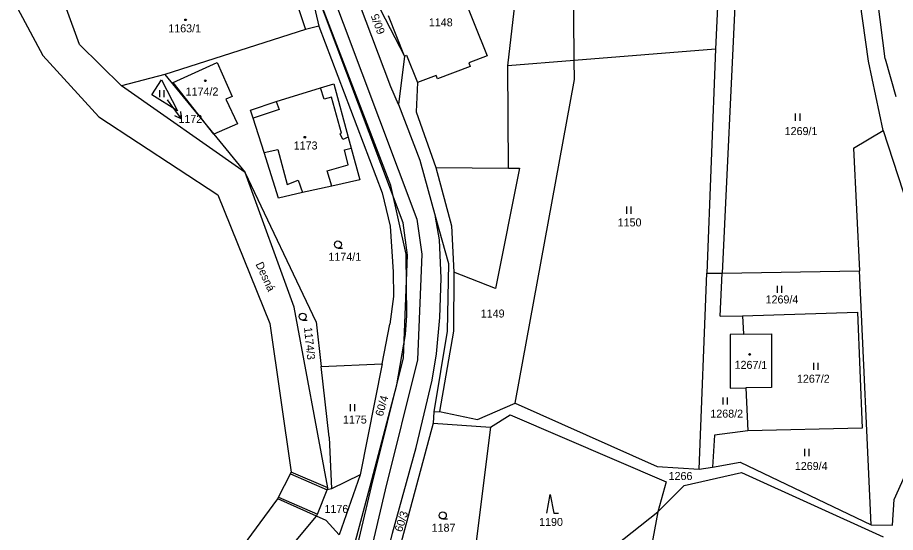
# Model space of a CAD drawing. Extents: x -670359 to -668019, y -978807 to -976674.
# Drawn here: x -670237.2 to -670050.9, y -978052.1 to -977942.9 of the extents above; entities that cross this region are included whole.
import ezdxf

# ---------------------------------------------------------------- set-up
doc = ezdxf.new("R2010")
doc.units = 0
for name, color, linetype in [('Hranice kat_území', 7, 'Continuous'), ('Hranice parcel', 7, 'Continuous'), ('Parcelní čísla', 7, 'Continuous'), ('Pop  PČ popisy', 7, 'Continuous'), ('Vnitřní kresba', 7, 'Continuous'), ('Věcná břemena k části', 7, 'Continuous'), ('Značky budov', 7, 'Continuous'), ('Značky kultur', 7, 'Continuous')]:
    doc.layers.add(name, color=color, linetype=linetype)

msp = doc.modelspace()

# ---------------------------------------------------------------- linework, layer by layer
at = {"layer": 'Hranice kat_území'}
for points in [[(-670237.25, -977940.88), (-670231.88, -977950.91)], [(-670231.88, -977950.91), (-670219.96, -977963.92)], [(-670219.96, -977963.92), (-670194.71, -977980.48)], [(-670194.71, -977980.48), (-670183.71, -978007.78)], [(-670183.71, -978007.78), (-670179.14, -978039.33)], [(-670181.84, -978044.64), (-670179.32, -978039.69)], [(-670179.32, -978039.69), (-670179.14, -978039.33)], [(-670206.64, -978078.45), (-670182.02, -978044.99)], [(-670182.02, -978044.99), (-670181.84, -978044.64)]]:
    msp.add_lwpolyline(points, dxfattribs=at)
at = {"layer": 'Hranice parcel'}
for points in [[(-670156.36, -977961.27), (-670157.99, -977957.53), (-670177.75, -977905.2), (-670177.61, -977904.51)], [(-670053.06, -977951.64), (-670057.82, -977914.27)], [(-670172.63, -978082.94), (-670171.28, -978083.15), (-670170.18, -978076.11), (-670165.52, -978053.97), (-670162.38, -978042.27), (-670156.72, -978020.75), (-670154.86, -978010.1), (-670154.63, -978006.17), (-670154.76, -977993.05), (-670158.01, -977978.52), (-670176.81, -977929.42)], [(-670176.81, -977929.42), (-670173.29, -977944.67)], [(-670180.87, -977931.18), (-670176.09, -977945.37)], [(-670224.12, -977948.54), (-670229.61, -977933.38)], [(-670164.29, -977933.2), (-670155.09, -977951.04)], [(-670119.06, -977951.97), (-670119.19, -977933.05)], [(-670056.57, -977952.14), (-670059, -977934.95)], [(-670133.18, -977953.11), (-670131.39, -977937.69)], [(-670088.41, -977935.95), (-670089.06, -977949.54)], [(-670084.73, -977935.93), (-670087.67, -977997.06)], [(-670173.29, -977944.67), (-670176.09, -977945.37)], [(-670173.29, -977944.67), (-670159.81, -977980.06)], [(-670176.09, -977945.37), (-670206.01, -977954.92)], [(-670215.17, -977957.33), (-670224.12, -977948.54)], [(-670089.06, -977949.54), (-670090.92, -977997.12)], [(-670204.19, -977956.66), (-670194.84, -977952.38), (-670191.69, -977959.57), (-670193, -977960.14), (-670190.54, -977965.39), (-670195.59, -977967.63)], [(-670155.09, -977951.04), (-670156.36, -977961.27)], [(-670155.09, -977951.04), (-670154.65, -977950.86)], [(-670154.65, -977950.86), (-670152.33, -977956.66)], [(-670119.03, -977956.01), (-670119.06, -977951.97)], [(-670053.5, -977966.83), (-670056.57, -977952.14)], [(-670053.06, -977951.64), (-670050.8, -977959.63)], [(-670133.01, -977974.79), (-670133.18, -977953.11)], [(-670208.76, -977959.22), (-670206.66, -977956.04)], [(-670206.66, -977956.04), (-670203.27, -977962.62)], [(-670206.01, -977954.92), (-670195.59, -977967.63)], [(-670131.57, -978024.69), (-670119.03, -977956.01)], [(-670188.93, -977975.76), (-670215.17, -977957.33)], [(-670195.59, -977967.63), (-670204.19, -977956.66)], [(-670182.37, -977960.69), (-670172.9, -977957.79)], [(-670172.9, -977957.79), (-670170.09, -977956.93)], [(-670170.09, -977956.93), (-670167.06, -977968.23)], [(-670152.33, -977956.66), (-670152.61, -977962.89)], [(-670203.27, -977962.62), (-670208.76, -977959.22)], [(-670187.83, -977962.47), (-670182.37, -977960.69)], [(-670156.36, -977961.27), (-670151.81, -977973.14)], [(-670187.25, -977964.17), (-670187.83, -977962.47)], [(-670152.61, -977962.89), (-670148.46, -977974.68)], [(-670184.92, -977971.47), (-670187.25, -977964.17)], [(-670059.75, -977970.54), (-670053.5, -977966.83)], [(-670053.5, -977966.83), (-670048.25, -977982.86)], [(-670195.59, -977967.63), (-670188.93, -977975.76)], [(-670167.06, -977968.23), (-670166.43, -977970.55)], [(-670166.43, -977970.55), (-670164.6, -977977.27)], [(-670059.75, -977970.54), (-670058.53, -977996.56)], [(-670181.82, -977981.14), (-670184.92, -977971.47)], [(-670151.81, -977973.14), (-670148.49, -977985.18)], [(-670148.46, -977974.68), (-670133.01, -977974.79)], [(-670178.55, -978004.33), (-670188.93, -977975.76)], [(-670173.87, -978007.38), (-670188.93, -977975.76)], [(-670170.5, -977978.6), (-670176.74, -977980)], [(-670164.6, -977977.27), (-670170.5, -977978.6)], [(-670176.74, -977980), (-670181.82, -977981.14)], [(-670159.81, -977980.06), (-670158.11, -977987.11)], [(-670163.67, -978098.07), (-670164.62, -978097.52), (-670164.93, -978097), (-670165.03, -978095.83), (-670164.26, -978085.83), (-670163.16, -978077.87), (-670159.11, -978058.23), (-670157.62, -978052.26), (-670152.59, -978034.05), (-670149.21, -978019.82), (-670148.28, -978014.22), (-670147.57, -978006.49), (-670147.34, -977998.17), (-670147.68, -977989.98), (-670148.49, -977985.18)], [(-670148.49, -977985.18), (-670147.83, -977987.72)], [(-670158.11, -977987.11), (-670157.54, -977996.79)], [(-670147.83, -977987.72), (-670145.77, -977995.05)], [(-670145.77, -977995.05), (-670146.04, -978009.36)], [(-670157.54, -977996.79), (-670157.43, -978002.07)], [(-670092.54, -978038.69), (-670090.92, -977997.12)], [(-670090.92, -977997.12), (-670087.67, -977997.06)], [(-670088.11, -978006.19), (-670087.67, -977997.06)], [(-670087.67, -977997.06), (-670058.53, -977996.56)], [(-670056, -978050.5), (-670058.53, -977996.56)], [(-670157.43, -978002.07), (-670158.19, -978007.91)], [(-670171.39, -978042.65), (-670178.55, -978004.33)], [(-670088.11, -978006.19), (-670083.31, -978006.16)], [(-670083.31, -978006.16), (-670058.93, -978005.38)], [(-670083.31, -978006.16), (-670083.13, -978010.04)], [(-670058.93, -978005.38), (-670057.91, -978029.98)], [(-670173.87, -978007.38), (-670172.79, -978016.92)], [(-670159.86, -978016.35), (-670158.19, -978007.91)], [(-670146.04, -978009.36), (-670148.89, -978026.54)], [(-670085.93, -978010.09), (-670085.95, -978021.52)], [(-670083.13, -978010.04), (-670085.93, -978010.09)], [(-670083.13, -978010.04), (-670077.21, -978009.96)], [(-670077.21, -978009.96), (-670077.15, -978021.31)], [(-670172.79, -978016.92), (-670159.86, -978016.35)], [(-670171.1, -978031.88), (-670172.79, -978016.92)], [(-670159.86, -978016.35), (-670164.52, -978039.85)], [(-670085.95, -978021.52), (-670082.62, -978021.44)], [(-670077.15, -978021.31), (-670082.62, -978021.44)], [(-670082.62, -978021.44), (-670082.22, -978030.53)], [(-670139.57, -978028.13), (-670131.57, -978024.69)], [(-670131.57, -978024.69), (-670101.43, -978038.09)], [(-670148.89, -978026.54), (-670148.99, -978028.93)], [(-670148.89, -978026.54), (-670147.69, -978026.47)], [(-670147.69, -978026.47), (-670139.57, -978028.13)], [(-670136.86, -978029.74), (-670132.64, -978027.16)], [(-670132.64, -978027.16), (-670099.57, -978041.37)], [(-670148.99, -978028.93), (-670159.63, -978068.36)], [(-670148.99, -978028.93), (-670136.86, -978029.74)], [(-670136.86, -978029.74), (-670140.01, -978055.12)], [(-670082.22, -978030.53), (-670089.25, -978031.45)], [(-670057.91, -978029.98), (-670082.22, -978030.53)], [(-670171.1, -978031.88), (-670170.63, -978042.84)], [(-670089.25, -978031.45), (-670089.69, -978038.25)], [(-670101.43, -978038.09), (-670092.54, -978038.69)], [(-670092.54, -978038.69), (-670089.69, -978038.25)], [(-670089.69, -978038.25), (-670083.87, -978037.17)], [(-670083.87, -978037.17), (-670056, -978050.5)], [(-670164.52, -978039.85), (-670170.63, -978042.84)], [(-670164.52, -978039.85), (-670168.99, -978052.57)], [(-670095.74, -978042.12), (-670083.53, -978039.41)], [(-670083.53, -978039.41), (-670053.47, -978053.05)], [(-670051.11, -978045.13), (-670048.27, -978038.64)], [(-670099.57, -978041.37), (-670101.33, -978047.75)], [(-670173.6, -978048.25), (-670171.55, -978043.02)], [(-670171.55, -978043.02), (-670171.39, -978042.65)], [(-670170.63, -978042.84), (-670171.55, -978043.02)], [(-670101.33, -978047.75), (-670095.74, -978042.12)], [(-670051.49, -978050.56), (-670051.11, -978045.13)], [(-670196.85, -978076.29), (-670173.76, -978048.61)], [(-670173.76, -978048.61), (-670173.6, -978048.25)], [(-670171.72, -978049.59), (-670173.76, -978048.61)], [(-670123.1, -978064.97), (-670101.33, -978047.75)], [(-670101.33, -978047.75), (-670103.12, -978057.29)], [(-670168.99, -978052.57), (-670171.72, -978049.59)], [(-670056, -978050.5), (-670051.49, -978050.56)]]:
    msp.add_lwpolyline(points, dxfattribs=at)
at = {"layer": 'Parcelní čísla'}
for p, q in [((-670205.49, -977960.3), (-670204.89, -977961.1)), ((-670202.68, -977962.82), (-670202.5, -977964.31))]:
    msp.add_line(p, q, dxfattribs=at)
msp.add_lwpolyline([(-670204.89, -977961.1), (-670202.5, -977964.31), (-670203.88, -977963.71)], dxfattribs=at)
at = {"layer": 'Vnitřní kresba'}
for points in [[(-670145.58, -977931.03), (-670137.56, -977951)], [(-670155.09, -977951.04), (-670158.47, -977942.46)], [(-670089.06, -977949.54), (-670119.06, -977951.97)], [(-670137.56, -977951), (-670141.45, -977952.49)], [(-670141.45, -977952.49), (-670141.18, -977953.22)], [(-670119.06, -977951.97), (-670133.18, -977953.11)], [(-670141.18, -977953.22), (-670148.08, -977955.89)], [(-670206.01, -977954.92), (-670215.17, -977957.33)], [(-670148.37, -977955.14), (-670152.33, -977956.66)], [(-670148.08, -977955.89), (-670148.37, -977955.14)], [(-670172.12, -977960.2), (-670172.9, -977957.79)], [(-670170.6, -977959.73), (-670172.12, -977960.2)], [(-670168.5, -977967.4), (-670170.6, -977959.73)], [(-670182.37, -977960.69), (-670181.74, -977962.37)], [(-670181.74, -977962.37), (-670187.25, -977964.17)], [(-670168.73, -977967.5), (-670168.5, -977967.4)], [(-670168.18, -977968.7), (-670168.73, -977967.5)], [(-670167.06, -977968.23), (-670168.18, -977968.7)], [(-670184.92, -977971.47), (-670182, -977970.84)], [(-670182, -977970.84), (-670180.01, -977978.3)], [(-670167.84, -977970.9), (-670166.43, -977970.55)], [(-670167.06, -977974.07), (-670167.84, -977970.9)], [(-670171.5, -977975.4), (-670167.06, -977974.07)], [(-670148.46, -977974.68), (-670145.1, -977987.02)], [(-670130.69, -977974.8), (-670135.76, -978000.36)], [(-670133.01, -977974.79), (-670130.69, -977974.8)], [(-670170.5, -977978.6), (-670171.5, -977975.4)], [(-670180.01, -977978.3), (-670177.68, -977977.35)], [(-670177.68, -977977.35), (-670176.74, -977980)], [(-670145.1, -977987.02), (-670144.62, -977996.86)], [(-670144.62, -977996.86), (-670144.68, -978009.37)], [(-670135.76, -978000.36), (-670144.62, -977996.86)], [(-670144.68, -978009.37), (-670147.69, -978026.47)], [(-670179.32, -978039.69), (-670171.55, -978043.02)], [(-670171.39, -978042.65), (-670179.14, -978039.33)], [(-670173.76, -978048.61), (-670182.02, -978044.99)], [(-670181.84, -978044.64), (-670173.6, -978048.25)]]:
    msp.add_lwpolyline(points, dxfattribs=at)
at = {"layer": 'Věcná břemena k části'}
for points in [[(-670231.37, -977794.32), (-670226.31, -977792.17), (-670203.33, -977848.99), (-670196.72, -977863.94), (-670192.84, -977861.8), (-670191.21, -977866.33), (-670191.12, -977866.56), (-670196.22, -977869.36), (-670195.63, -977870.79), (-670152.49, -977985.64), (-670151.43, -977993.09), (-670152.31, -978015.47), (-670159.21, -978043.03)], [(-670159.21, -978043.03), (-670166.44, -978073.84), (-670169.93, -978096.39), (-670171.6, -978117.05), (-670173.62, -978117.69), (-670174.87, -978118.08), (-670174.67, -978116.45), (-670172.91, -978096.03), (-670169.38, -978073.26), (-670162.13, -978042.33), (-670155.29, -978015.05), (-670154.43, -977993.25), (-670155.41, -977986.38), (-670176.81, -977929.42), (-670177.71, -977925.53), (-670186.89, -977901.98), (-670197.75, -977874.12), (-670224.71, -977806.51), (-670226.38, -977803.45)]]:
    msp.add_lwpolyline(points, dxfattribs=at)
at = {"layer": 'Značky budov'}
for centre in [(-670201.58, -977943.34), (-670197.4, -977956.27), (-670176.26, -977968.25), (-670081.82, -978014.34)]:
    msp.add_circle(centre, 0.175, dxfattribs=at)
at = {"layer": 'Značky kultur'}
for p, q in [((-670207.12, -977958.25), (-670207.12, -977959.75)), ((-670206.12, -977959.75), (-670206.12, -977958.25)), ((-670072.13, -977963.24), (-670072.13, -977964.74)), ((-670071.13, -977964.74), (-670071.13, -977963.24)), ((-670107.98, -977982.97), (-670107.98, -977984.47)), ((-670106.98, -977984.47), (-670106.98, -977982.97)), ((-670169.23, -977991.76), (-670168.23, -977991.76)), ((-670075.97, -977999.78), (-670075.97, -978001.28)), ((-670074.97, -978001.28), (-670074.97, -977999.78)), ((-670176.73, -978007.05), (-670175.73, -978007.05)), ((-670068.28, -978016.13), (-670068.28, -978017.63)), ((-670067.28, -978017.63), (-670067.28, -978016.13)), ((-670087.51, -978023.44), (-670087.51, -978024.94)), ((-670086.51, -978024.94), (-670086.51, -978023.44)), ((-670166.65, -978024.9), (-670166.65, -978026.4)), ((-670165.65, -978026.4), (-670165.65, -978024.9)), ((-670070.17, -978034.38), (-670070.17, -978035.88)), ((-670069.17, -978035.88), (-670069.17, -978034.38)), ((-670146.98, -978049.24), (-670145.98, -978049.24))]:
    msp.add_line(p, q, dxfattribs=at)
msp.add_lwpolyline([(-670124.91, -978048.02), (-670124.16, -978044.02), (-670123.41, -978048.02), (-670122.41, -978048.02)], dxfattribs=at)
for centre, radius in [((-670201.58, -977943.34), 0.175), ((-670197.4, -977956.27), 0.175), ((-670176.26, -977968.25), 0.175), ((-670169.23, -977991.01), 0.75), ((-670176.73, -978006.3), 0.75), ((-670081.82, -978014.34), 0.175), ((-670146.98, -978048.49), 0.75)]:
    msp.add_circle(centre, radius, dxfattribs=at)

# ---------------------------------------------------------------- texts
at = {"layer": 'Parcelní čísla'}
for s, rotation, p in [('60/5', 110.1673, (-670159.17, -977946.03)), ('1174/3', 275.7862, (-670176.44, -978008.61)), ('1267/1', 359.4881, (-670085.03, -978017.37)), ('60/4', 74.1647, (-670159.72, -978027.59)), ('60/3', 72.2639, (-670155.64, -978052.12))]:
    msp.add_text(s, height=1.7, rotation=rotation, dxfattribs=at).set_placement(p)
for s, height, p in [('1148', 1.7, (-670149.93, -977944.72)), ('1163/1', 1.7, (-670205.25, -977946)), ('1174/2', 1.7, (-670201.56, -977959.4)), ('1172', 0.1, (-670205.49, -977960.3)), ('1172', 1.7, (-670203.1, -977965.21)), ('1269/1', 1.7, (-670074.39, -977967.79)), ('1173', 1.7, (-670178.62, -977970.85)), ('1150', 1.7, (-670109.84, -977987.17)), ('1174/1', 1.7, (-670171.25, -977994.45)), ('1269/4', 1.7, (-670078.44, -978003.51)), ('1149', 1.7, (-670138.91, -978006.5)), ('1267/2', 1.7, (-670071.78, -978020.33)), ('1268/2', 1.7, (-670090.17, -978027.74)), ('1175', 1.7, (-670168.17, -978029)), ('1269/4', 1.7, (-670072.23, -978038.85)), ('1266', 1.7, (-670099.03, -978040.97)), ('1176', 1.7, (-670172.09, -978047.96)), ('1190', 1.7, (-670126.52, -978050.72)), ('1187', 1.7, (-670149.34, -978051.94))]:
    msp.add_text(s, height=height, dxfattribs=at).set_placement(p)
at = {"layer": 'Pop  PČ popisy'}
msp.add_text('Desná', height=1.7, rotation=294.7156, dxfattribs=at).set_placement((-670186.77, -977995.18))

doc.saveas('drawing.dxf')
